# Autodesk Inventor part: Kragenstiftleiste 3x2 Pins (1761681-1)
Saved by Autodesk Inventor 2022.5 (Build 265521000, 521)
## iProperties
Created: 2024-12
Part Number: Kragenstiftleiste 3x2 Pins (1761681-1)
Material: Generic
Document SubType Name: Modeling
Designer: AdminForWorker
Density: 1 g/cm^3
Appearance: Default
Title: Kragenstiftleiste 3x2 Pins (1761681-1)
Author: AdminForWorker
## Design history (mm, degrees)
feature "Body1"
body "Solid1"
